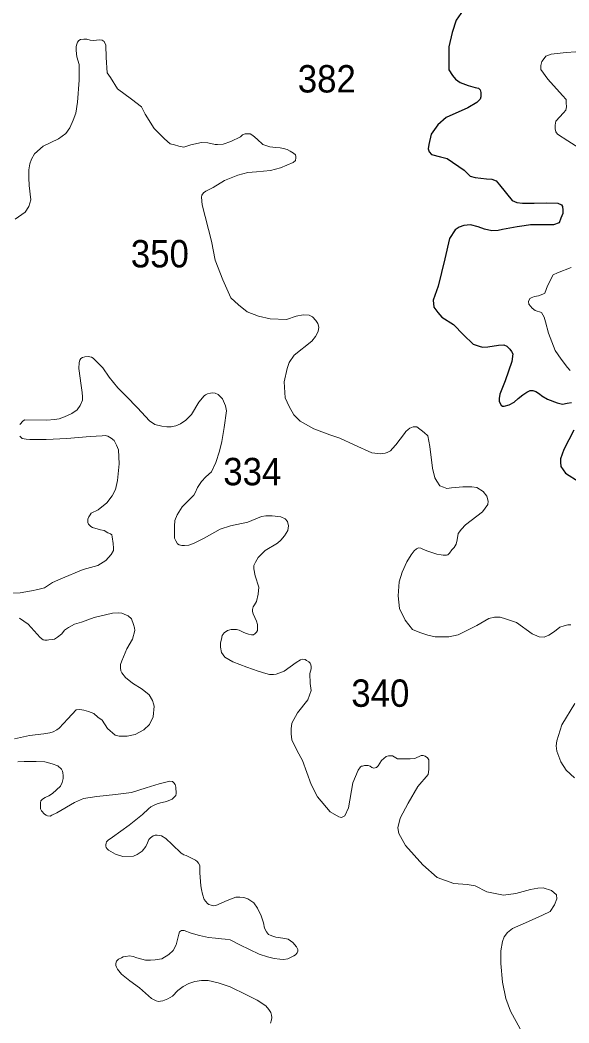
# Model space of a CAD drawing. Extents: x 445.4 to 500, y 8728.7 to 8784.
# Drawn here: x 471.62 to 474.83, y 8758.07 to 8763.93 of the extents above; entities that cross this region are included whole.
import ezdxf

# ---------------------------------------------------------------- set-up
doc = ezdxf.new("R2010")
doc.units = 0
doc.header["$LTSCALE"] = 0.064
doc.layers.add('1', color=7, linetype='Continuous', lineweight=25)
doc.layers.add('2', color=7, linetype='Continuous', lineweight=13)
doc.layers.add('21', color=7, linetype='Continuous')

msp = doc.modelspace()

# ---------------------------------------------------------------- linework, layer by layer
at = {"layer": '1'}
for points in [[(474.2089, 8763.9897), (474.1671, 8763.9313), (474.1437, 8763.8594), (474.1252, 8763.7747), (474.1252, 8763.6411), (474.147, 8763.6077), (474.1637, 8763.586), (474.1921, 8763.5659), (474.2373, 8763.5492), (474.2791, 8763.5376), (474.2992, 8763.5342), (474.3075, 8763.5242), (474.3125, 8763.5075), (474.3124, 8763.4831), (474.3073, 8763.4681), (474.2889, 8763.4497), (474.2354, 8763.418), (474.11, 8763.3628), (474.0615, 8763.3194), (474.0214, 8763.2643), (474.008, 8763.2042), (474.0046, 8763.1791), (474.0097, 8763.1608), (474.0247, 8763.1457), (474.0766, 8763.1324), (474.115, 8763.1223), (474.2146, 8763.0531), (474.2497, 8763.0197), (474.2781, 8763.0113), (474.345, 8763.003), (474.3768, 8763.0013), (474.4019, 8762.9913), (474.422, 8762.9679), (474.4955, 8762.8777), (474.5223, 8762.866), (474.5557, 8762.861), (474.6226, 8762.861), (474.6929, 8762.8627), (474.7614, 8762.861), (474.7832, 8762.851), (474.7899, 8762.8409), (474.7915, 8762.8209), (474.7915, 8762.8009), (474.7798, 8762.7741), (474.7698, 8762.7457), (474.7355, 8762.7354), (474.6017, 8762.7338), (474.5649, 8762.7288), (474.5248, 8762.7238), (474.4813, 8762.7154), (474.4379, 8762.7081), (474.4128, 8762.702), (474.376, 8762.7004), (474.3342, 8762.7087), (474.2957, 8762.7238), (474.2522, 8762.7354), (474.2121, 8762.7304), (474.1853, 8762.7204), (474.1619, 8762.7054), (474.1285, 8762.6553)], [(474.1285, 8762.6553), (474.1013, 8762.5356), (474.0628, 8762.3769), (474.0344, 8762.2951), (474.0377, 8762.2533), (474.0612, 8762.2216), (474.084, 8762.1943), (474.1526, 8762.1526), (474.2113, 8762.0908), (474.2663, 8762.0373), (474.3031, 8762.0257), (474.3215, 8762.0206), (474.3533, 8762.0223), (474.4151, 8762.0323), (474.4469, 8762.034), (474.4636, 8762.0257), (474.482, 8762.0089), (474.4921, 8761.9939), (474.4987, 8761.9806), (474.4938, 8761.9358), (474.4536, 8761.8223), (474.4235, 8761.7454), (474.4185, 8761.7204), (474.4185, 8761.702), (474.4302, 8761.6803), (474.4386, 8761.6753), (474.4489, 8761.6758), (474.477, 8761.682), (474.5071, 8761.6987), (474.5305, 8761.7199), (474.5573, 8761.7404), (474.5807, 8761.7571), (474.6008, 8761.7655), (474.6158, 8761.7672), (474.6342, 8761.7605), (474.6543, 8761.7471), (474.6677, 8761.7354), (474.7017, 8761.7154), (474.7569, 8761.6936), (474.7887, 8761.687), (474.8171, 8761.692), (474.8422, 8761.697)], [(474.8554, 8761.5339), (474.7969, 8761.422), (474.7768, 8761.3669), (474.7768, 8761.3468), (474.7801, 8761.3218), (474.8069, 8761.2834), (474.8855, 8761.2333)]]:
    msp.add_lwpolyline(points, dxfattribs=at)
at = {"layer": '2'}
for points in [[(471.5923, 8762.7668), (471.6508, 8762.8092), (471.6714, 8762.8413), (471.684, 8762.8813), (471.6748, 8762.9649), (471.6714, 8763.0084), (471.6718, 8763.0551), (471.6775, 8763.0906), (471.6879, 8763.1192), (471.7062, 8763.1501), (471.7566, 8763.1948), (471.8449, 8763.2371), (471.8884, 8763.268), (471.9125, 8763.3012), (471.932, 8763.347), (471.9474, 8763.3867), (471.9555, 8763.452), (471.9658, 8763.5802), (471.9658, 8763.6718), (471.9518, 8763.7173), (471.9495, 8763.754), (471.9495, 8763.7769), (471.9518, 8763.7906), (471.9564, 8763.802), (471.9644, 8763.8123), (471.9747, 8763.8181), (471.9942, 8763.8204)], [(471.9942, 8763.8204), (472.0114, 8763.8204), (472.0309, 8763.8135), (472.0481, 8763.8112), (472.0676, 8763.8135), (472.0836, 8763.8158), (472.1008, 8763.8146), (472.1123, 8763.8066), (472.1214, 8763.7837), (472.1237, 8763.7127), (472.1299, 8763.6238), (472.1482, 8763.5952), (472.1906, 8763.5288), (472.272, 8763.4681), (472.3293, 8763.4235), (472.3513, 8763.3816), (472.4051, 8763.2969), (472.4647, 8763.2373), (472.4968, 8763.2087), (472.5221, 8763.2018), (472.5473, 8763.1938), (472.5771, 8763.1892), (472.6183, 8763.2018), (472.6809, 8763.2164), (472.7176, 8763.2141), (472.76, 8763.2038), (472.7749, 8763.2038), (472.807, 8763.2061), (472.8528, 8763.2221), (472.909, 8763.2496), (472.9193, 8763.2599), (472.936, 8763.2665), (472.9518, 8763.2671), (472.9657, 8763.2665), (472.9803, 8763.2572), (473.0065, 8763.2345), (473.039, 8763.2037), (473.0794, 8763.1895), (473.1138, 8763.1871), (473.1399, 8763.1847), (473.1601, 8763.18), (473.1814, 8763.1753), (473.1992, 8763.1658), (473.2182, 8763.1527), (473.2289, 8763.1444), (473.2325, 8763.1349), (473.2325, 8763.1255), (473.2301, 8763.1112), (473.2159, 8763.0994), (473.1411, 8763.0685), (473.0829, 8763.0519), (473.0022, 8763.0448), (472.9512, 8763.0401), (472.893, 8763.0247), (472.8155, 8762.993), (472.7478, 8762.9527), (472.7051, 8762.9313), (472.6932, 8762.9218), (472.6825, 8762.9088), (472.6801, 8762.8957), (472.6849, 8762.8507), (472.7395, 8762.6384), (472.7611, 8762.5283), (472.805, 8762.4133), (472.8513, 8762.3089), (472.8964, 8762.2662), (472.9467, 8762.2262), (473.0132, 8762.2001), (473.0821, 8762.1847), (473.177, 8762.1823), (473.2328, 8762.2001), (473.2744, 8762.2084), (473.3088, 8762.2072), (473.329, 8762.1966), (473.348, 8762.1764), (473.361, 8762.1586), (473.3658, 8762.1361), (473.3622, 8762.1112), (473.3456, 8762.0827), (473.3242, 8762.0543), (473.221, 8761.9737), (473.1935, 8761.9303), (473.1804, 8761.8947), (473.1638, 8761.8177), (473.1685, 8761.724), (473.1923, 8761.673), (473.2196, 8761.6244), (473.2569, 8761.5878), (473.3364, 8761.5416), (473.4302, 8761.5072), (473.4895, 8761.4882), (473.5726, 8761.4491), (473.6747, 8761.4029), (473.71, 8761.3982), (473.7266, 8761.3958), (473.7527, 8761.4006), (473.7646, 8761.4041), (473.7836, 8761.4136), (473.7967, 8761.4267), (473.8157, 8761.4492), (473.8667, 8761.5144)], [(474.8846, 8763.1852), (474.8205, 8763.2255), (474.7592, 8763.2645), (474.7494, 8763.2784), (474.7452, 8763.2952), (474.7452, 8763.3174), (474.7508, 8763.3397), (474.794, 8763.3884), (474.808, 8763.4052), (474.8121, 8763.4246), (474.8107, 8763.4483), (474.8107, 8763.4678), (474.7886, 8763.491), (474.7036, 8763.5857), (474.6632, 8763.6428), (474.6632, 8763.6651), (474.6687, 8763.6887), (474.6757, 8763.6985), (474.691, 8763.7194), (474.7231, 8763.7319), (474.8095, 8763.7417), (474.9239, 8763.7486)], [(474.8344, 8761.8835), (474.8191, 8761.9002), (474.7814, 8761.9503), (474.7463, 8762.0001), (474.7073, 8762.1018), (474.6905, 8762.1686), (474.6822, 8762.1951), (474.6668, 8762.2215), (474.6292, 8762.2341), (474.6111, 8762.248), (474.5915, 8762.2716), (474.5901, 8762.287), (474.5985, 8762.3037), (474.6055, 8762.3078), (474.625, 8762.3162), (474.6487, 8762.319), (474.6738, 8762.3287), (474.685, 8762.3343), (474.7017, 8762.3789), (474.7351, 8762.4429), (474.7593, 8762.455), (474.8388, 8762.4843)], [(471.6204, 8761.5679), (471.6396, 8761.5897), (471.6487, 8761.5943), (471.7764, 8761.5934), (471.822, 8761.597), (471.8485, 8761.6007), (471.8804, 8761.6125), (471.9224, 8761.6317), (471.9543, 8761.6526), (471.9729, 8761.6796), (471.9848, 8761.7097), (471.9848, 8761.7297), (471.9839, 8761.7553), (471.9784, 8761.7954), (471.9638, 8761.8947), (471.9656, 8761.9292), (471.9702, 8761.9428), (471.9756, 8761.9528), (471.9857, 8761.9601), (471.9993, 8761.9638), (472.0194, 8761.9656), (472.0377, 8761.962)], [(472.0377, 8761.962), (472.0486, 8761.9547), (472.1043, 8761.8982), (472.1417, 8761.8444), (472.1913, 8761.7817), (472.2405, 8761.7334), (472.3062, 8761.665), (472.3765, 8761.5885), (472.4084, 8761.5684), (472.4486, 8761.5575), (472.4787, 8761.5547), (472.5042, 8761.5547), (472.5307, 8761.5602), (472.5571, 8761.572), (472.59, 8761.5939), (472.6218, 8761.6266), (472.6656, 8761.6977), (472.6957, 8761.736), (472.7048, 8761.7414), (472.7158, 8761.7469), (472.7322, 8761.7506), (472.7422, 8761.7524), (472.7605, 8761.7515), (472.7787, 8761.7433), (472.8024, 8761.7168), (472.8207, 8761.6767), (472.8262, 8761.6467), (472.8134, 8761.5501), (472.7997, 8761.4693), (472.7851, 8761.4119), (472.7641, 8761.3463), (472.7395, 8761.2907), (472.7055, 8761.2617), (472.68, 8761.2353), (472.6563, 8761.1997), (472.6444, 8761.1688), (472.6362, 8761.1542), (472.6161, 8761.136), (472.5669, 8761.0858), (472.5386, 8761.0394), (472.524, 8761.0065), (472.5238, 8760.973), (472.5238, 8760.9174), (472.5238, 8760.9037), (472.5311, 8760.8873), (472.5411, 8760.8709), (472.5511, 8760.8646), (472.5648, 8760.8609), (472.5812, 8760.8609), (472.6068, 8760.8618), (472.6369, 8760.8746), (472.6962, 8760.9028), (472.7902, 8760.9557), (472.8492, 8760.9761), (472.9514, 8760.9971), (473.0317, 8761.0299), (473.0573, 8761.0345), (473.0938, 8761.0345), (473.143, 8761.0281), (473.1686, 8761.0162), (473.1832, 8761.0007), (473.1895, 8760.9761), (473.185, 8760.9488), (473.1658, 8760.9178), (473.144, 8760.8916), (473.1249, 8760.8743), (473.0528, 8760.8305), (473.0117, 8760.7913), (472.9953, 8760.764), (472.9862, 8760.744), (472.9853, 8760.7248), (472.9944, 8760.6838), (473.0163, 8760.6164), (473.0108, 8760.5757), (473.0026, 8760.5338), (472.9898, 8760.5138), (472.9825, 8760.5028), (472.978, 8760.4864), (472.978, 8760.4755), (472.9816, 8760.4618), (473.0026, 8760.419), (473.0072, 8760.3991), (473.0081, 8760.3827), (473.0072, 8760.3645), (473.0017, 8760.3545), (472.9944, 8760.3472), (472.9835, 8760.339), (472.9735, 8760.3381), (472.9552, 8760.3417), (472.9379, 8760.3481), (472.9242, 8760.3545), (472.9132, 8760.36), (472.9005, 8760.3663), (472.8859, 8760.37), (472.8767, 8760.37), (472.8543, 8760.369), (472.8324, 8760.3636), (472.8132, 8760.3508), (472.8004, 8760.3344), (472.7968, 8760.3134), (472.7922, 8760.2916)], [(473.8667, 8761.5144), (473.8738, 8761.5274), (473.8869, 8761.5381), (473.8976, 8761.5464), (473.9177, 8761.5535), (473.9391, 8761.5535), (473.9807, 8761.5215), (474.002, 8761.5014), (474.0151, 8761.4385), (474.0293, 8761.3116), (474.0426, 8761.2563), (474.0545, 8761.2361), (474.0735, 8761.21), (474.0937, 8761.2017), (474.1138, 8761.1946), (474.1411, 8761.197), (474.2064, 8761.2041), (474.2598, 8761.2041), (474.2895, 8761.1993), (474.3251, 8761.1756), (474.3465, 8761.1495), (474.3548, 8761.1199), (474.3524, 8761.0997), (474.3216, 8761.0571), (474.2219, 8760.9812), (474.1994, 8760.9566), (474.1792, 8760.9305), (474.1733, 8760.8937), (474.1673, 8760.8688), (474.1566, 8760.8487), (474.1424, 8760.8344), (474.1293, 8760.8167), (474.1187, 8760.806), (474.1115, 8760.8048), (474.0925, 8760.8048), (474.0807, 8760.806), (474.0557, 8760.8095), (473.9964, 8760.8285), (473.9726, 8760.8392), (473.962, 8760.8451), (473.962, 8760.8451), (473.9477, 8760.8463), (473.937, 8760.8416), (473.9228, 8760.8285), (473.905, 8760.806), (473.8789, 8760.7657), (473.8523, 8760.7046), (473.8357, 8760.6477), (473.8297, 8760.5671), (473.8368, 8760.4924), (473.8701, 8760.4236), (473.9131, 8760.3705), (473.9557, 8760.3518), (474.0019, 8760.3364), (474.0454, 8760.3262), (474.089, 8760.3262), (474.1249, 8760.3262), (474.1788, 8760.339), (474.289, 8760.3928), (474.3583, 8760.4338), (474.3916, 8760.4414), (474.4249, 8760.4414), (474.4557, 8760.4312), (474.5198, 8760.4107), (474.6121, 8760.3441), (474.6531, 8760.3262), (474.6817, 8760.3246), (474.7083, 8760.3361), (474.7419, 8760.3581), (474.7743, 8760.3824), (474.7986, 8760.3917), (474.8206, 8760.3963), (474.838, 8760.3963)], [(471.5724, 8760.5812), (471.6217, 8760.5839), (471.6874, 8760.5948), (471.7239, 8760.6039), (471.7631, 8760.614), (471.8113, 8760.6445), (471.8587, 8760.6664), (471.9901, 8760.7202), (472.0749, 8760.7439), (472.1224, 8760.773), (472.1534, 8760.8076), (472.1662, 8760.8304), (472.1662, 8760.8459), (472.1643, 8760.8724), (472.1581, 8760.9105), (472.1563, 8760.9223), (472.1499, 8760.9287), (472.1344, 8760.9351), (472.1116, 8760.9478), (472.0906, 8760.9515), (472.0432, 8760.966), (472.0341, 8760.9724), (472.0259, 8760.9797), (472.0213, 8760.9861), (472.0158, 8760.9952), (472.0158, 8761.0052), (472.0176, 8761.0153), (472.0222, 8761.028), (472.0295, 8761.0399), (472.0359, 8761.049), (472.0779, 8761.069), (472.128, 8761.11), (472.1581, 8761.151), (472.1783, 8761.1881), (472.1902, 8761.2401), (472.1993, 8761.3376), (472.1957, 8761.4202), (472.1847, 8761.4467), (472.1711, 8761.474), (472.1537, 8761.4886), (472.1336, 8761.4995), (472.1172, 8761.5032), (472.1008, 8761.5022), (472.0296, 8761.4977), (471.8941, 8761.4859), (471.7728, 8761.4804), (471.7098, 8761.4795), (471.6779, 8761.4795), (471.6569, 8761.4813), (471.6341, 8761.4868), (471.625, 8761.4941), (471.6204, 8761.5004)], [(471.5884, 8759.7315), (471.6752, 8759.7493), (471.759, 8759.7602), (471.7954, 8759.7665), (471.8136, 8759.772), (471.8354, 8759.7829), (471.85, 8759.7938), (471.8992, 8759.8466), (471.9492, 8759.8993), (471.9709, 8759.902), (471.993, 8759.8986), (472.0202, 8759.8901), (472.0509, 8759.8782), (472.0747, 8759.8578), (472.1003, 8759.8391), (472.1309, 8759.7915), (472.1769, 8759.7523), (472.2007, 8759.7455), (472.216, 8759.7455), (472.2467, 8759.7455), (472.2926, 8759.7557), (472.3437, 8759.783), (472.3778, 8759.8136), (472.3982, 8759.8595), (472.404, 8759.9216), (472.4003, 8759.9343), (472.3939, 8759.9553), (472.3748, 8759.9872), (472.3346, 8760.0218), (472.2781, 8760.0565), (472.2368, 8760.089), (472.2149, 8760.1155), (472.2085, 8760.1282), (472.2067, 8760.1465), (472.2076, 8760.1647), (472.2149, 8760.1856), (472.245, 8760.2567), (472.2778, 8760.3132), (472.2907, 8760.3632), (472.2889, 8760.3787), (472.2834, 8760.3996), (472.2715, 8760.4315), (472.2524, 8760.4497), (472.2287, 8760.4598), (472.215, 8760.4643), (472.1958, 8760.4661), (472.1602, 8760.4652), (472.0535, 8760.4388), (471.9789, 8760.4131), (471.9388, 8760.4003), (471.9032, 8760.3812), (471.8804, 8760.3648), (471.8649, 8760.3447), (471.8393, 8760.3256), (471.8229, 8760.3137), (471.812, 8760.311), (471.7891, 8760.3083)], [(471.7891, 8760.3083), (471.78, 8760.3074), (471.7663, 8760.3074), (471.7563, 8760.3092), (471.739, 8760.3229), (471.6678, 8760.4012), (471.6185, 8760.4368)], [(472.7922, 8760.2916), (472.7922, 8760.266), (472.7977, 8760.2351), (472.8169, 8760.2077), (472.8634, 8760.1804), (472.9455, 8760.1503), (473.0109, 8760.1253), (473.0556, 8760.1126), (473.0784, 8760.1071), (473.1012, 8760.1062), (473.1176, 8760.1089), (473.1642, 8760.1253), (473.2335, 8760.1763), (473.259, 8760.1927), (473.2718, 8760.1955), (473.2855, 8760.1937), (473.2937, 8760.1891), (473.3083, 8760.1809), (473.3147, 8760.1727), (473.3193, 8760.1627), (473.3202, 8760.1536), (473.3202, 8760.1399), (473.3129, 8760.1126), (473.3156, 8760.0533), (473.3211, 8760.0132), (473.3007, 8759.9584), (473.2407, 8759.8835), (473.2085, 8759.8214), (473.2042, 8759.7892), (473.2042, 8759.7593), (473.2085, 8759.725), (473.2385, 8759.6607), (473.271, 8759.6037), (473.3203, 8759.4645), (473.3589, 8759.3917), (473.4318, 8759.3039), (473.4832, 8759.2739), (473.4982, 8759.2718), (473.5175, 8759.2803), (473.539, 8759.3275), (473.5647, 8759.4731), (473.5962, 8759.5482), (473.6083, 8759.5669), (473.6149, 8759.5713), (473.6204, 8759.5713), (473.6325, 8759.5757), (473.6534, 8759.5757), (473.6666, 8759.5702), (473.6754, 8759.5636), (473.6864, 8759.5592), (473.7018, 8759.5625), (473.7128, 8759.5735), (473.7315, 8759.6031), (473.76, 8759.6273), (473.7721, 8759.6317), (473.7952, 8759.6306), (473.8249, 8759.6141), (473.8601, 8759.613), (473.8986, 8759.613), (473.9261, 8759.6152), (473.9636, 8759.6341), (473.975, 8759.6341), (473.9865, 8759.6284), (473.9865, 8759.6284), (473.9998, 8759.6189), (474.0074, 8759.6075), (474.0074, 8759.5505), (474.0036, 8759.522), (473.9446, 8759.4517), (473.8875, 8759.3548), (473.84, 8759.2674), (473.8267, 8759.2104), (473.8328, 8759.1765), (473.8728, 8759.1081), (473.9736, 8758.9941), (474.0573, 8758.92), (474.1543, 8758.8858), (474.2323, 8758.8801), (474.2798, 8758.8725), (474.3464, 8758.8364), (474.4453, 8758.8174), (474.5167, 8758.8267), (474.6023, 8758.8495), (474.6441, 8758.8571), (474.6764, 8758.859), (474.724, 8758.8438), (474.7544, 8758.8191), (474.7553, 8758.795), (474.7419, 8758.7609), (474.716, 8758.7216), (474.6725, 8758.7009), (474.5897, 8758.6637), (474.4966, 8758.6213), (474.4676, 8758.5996), (474.4479, 8758.5737), (474.4386, 8758.5469), (474.4283, 8758.491), (474.4283, 8758.4179), (474.4386, 8758.3083), (474.4572, 8758.2132), (474.4853, 8758.139)], [(474.8612, 8759.9374), (474.7848, 8759.8125), (474.7566, 8759.718), (474.752, 8759.6891), (474.7554, 8759.659), (474.7797, 8759.5966)], [(471.8349, 8759.298), (471.8058, 8759.2844), (471.7976, 8759.2789), (471.7803, 8759.2799), (471.773, 8759.2853), (471.763, 8759.2899), (471.7457, 8759.3099), (471.7412, 8759.3217), (471.7403, 8759.3381), (471.7412, 8759.3562), (471.743, 8759.369), (471.7521, 8759.3781), (471.7676, 8759.3872), (471.7894, 8759.3981), (471.8095, 8759.4117), (471.8568, 8759.4545), (471.8668, 8759.4754), (471.873, 8759.4987), (471.8721, 8759.5169), (471.8712, 8759.5324), (471.8685, 8759.5424), (471.8621, 8759.5533), (471.8412, 8759.5733), (471.8093, 8759.5842), (471.7656, 8759.5961), (471.7146, 8759.5988), (471.6445, 8759.5979), (471.6081, 8759.597)], [(474.7797, 8759.5966), (474.811, 8759.548), (474.8596, 8759.5029)], [(473.1054, 8758.4474), (473.1388, 8758.4424), (473.1588, 8758.4407), (473.1855, 8758.4457), (473.2198, 8758.4625), (473.2298, 8758.4691), (473.2398, 8758.4791), (473.2431, 8758.4891), (473.2431, 8758.4991), (473.2348, 8758.5141), (473.2131, 8758.5408), (473.1864, 8758.5591), (473.1564, 8758.5658), (473.1146, 8758.5708), (473.098, 8758.5775), (473.0813, 8758.5825), (473.0713, 8758.5875), (473.0596, 8758.6025), (473.0479, 8758.6242), (473.0425, 8758.6562), (473.0288, 8758.6962), (473.0079, 8758.7417), (472.987, 8758.7726), (472.9505, 8758.7953), (472.9269, 8758.8035), (472.9041, 8758.8053), (472.8804, 8758.8044), (472.8304, 8758.7853), (472.7648, 8758.7571), (472.7521, 8758.7553), (472.7375, 8758.758), (472.7238, 8758.7617), (472.7166, 8758.768), (472.6965, 8758.7926), (472.6874, 8758.8235), (472.681, 8758.8508), (472.6765, 8758.8717), (472.6718, 8758.9478), (472.6709, 8758.9724), (472.6709, 8758.9897), (472.6636, 8759.0042), (472.6554, 8759.0133), (472.6463, 8759.0224), (472.619, 8759.0361), (472.5916, 8759.0479), (472.5771, 8759.0533), (472.5707, 8759.057), (472.5616, 8759.0633), (472.5094, 8759.1138), (472.473, 8759.1484), (472.4466, 8759.1629), (472.4338, 8759.1665), (472.422, 8759.1684), (472.4093, 8759.1674), (472.3992, 8759.1647), (472.3829, 8759.1529), (472.3728, 8759.142), (472.3646, 8759.122), (472.3555, 8759.1011), (472.3337, 8759.0747), (472.3055, 8759.0556), (472.2836, 8759.0456), (472.2217, 8759.0429), (472.1783, 8759.0574), (472.151, 8759.0719), (472.1383, 8759.0792), (472.1301, 8759.0874), (472.1246, 8759.0965), (472.1228, 8759.1038), (472.1219, 8759.1111), (472.1237, 8759.1211), (472.1264, 8759.1292), (472.1346, 8759.1383), (472.1601, 8759.1556), (472.2575, 8759.2256), (472.3358, 8759.2893), (472.371, 8759.3208), (472.3847, 8759.3335), (472.401, 8759.3408), (472.422, 8759.3499), (472.442, 8759.3562), (472.4684, 8759.3626), (472.4857, 8759.369), (472.5094, 8759.3781), (472.5194, 8759.3872), (472.5258, 8759.3944), (472.5303, 8759.399), (472.533, 8759.4108), (472.5312, 8759.449), (472.5267, 8759.4636), (472.5185, 8759.4736), (472.5121, 8759.4817), (472.4957, 8759.4836), (472.4329, 8759.4681), (472.3582, 8759.4445), (472.2708, 8759.4172), (472.1782, 8759.4044), (472.0698, 8759.3944), (471.9906, 8759.3826), (471.9396, 8759.359), (471.8349, 8759.298)], [(473.0835, 8758.0696), (473.0889, 8758.0875), (473.0907, 8758.1028), (473.0898, 8758.1162), (473.0853, 8758.1305), (473.0736, 8758.1494), (473.0557, 8758.1709), (473.0053, 8758.2038), (472.9443, 8758.2351), (472.8483, 8758.2817), (472.7783, 8758.305), (472.72, 8758.3176), (472.6814, 8758.3176), (472.6419, 8758.3122), (472.6061, 8758.3006), (472.5732, 8758.2834), (472.5418, 8758.2592), (472.5104, 8758.2269), (472.4834, 8758.2117), (472.4646, 8758.2036), (472.4538, 8758.2), (472.4413, 8758.1982), (472.4287, 8758.1964), (472.4161, 8758.2), (472.3892, 8758.2135), (472.3193, 8758.2753), (472.2627, 8758.3156), (472.2134, 8758.3551), (472.1899, 8758.3842), (472.1846, 8758.3959), (472.1801, 8758.4058), (472.1801, 8758.4174), (472.1837, 8758.4317), (472.1962, 8758.4425), (472.2124, 8758.4515), (472.224, 8758.4559), (472.2393, 8758.4595), (472.2608, 8758.4622), (472.2824, 8758.4595), (472.3021, 8758.4506), (472.3532, 8758.438), (472.3819, 8758.438), (472.4098, 8758.4398), (472.4483, 8758.4443), (472.4905, 8758.4703), (472.5156, 8758.4936), (472.5336, 8758.5276), (472.5479, 8758.5886), (472.5524, 8758.6029), (472.5641, 8758.611), (472.5793, 8758.6101), (472.6201, 8758.5943), (472.6685, 8758.5818), (472.7215, 8758.5692), (472.7618, 8758.5657), (472.7977, 8758.5621), (472.8192, 8758.5603), (472.8471, 8758.5567), (472.9051, 8758.5274), (473.017, 8758.4724), (473.067, 8758.4557), (473.1054, 8758.4474)], [(474.4853, 8758.139), (474.5412, 8758.0356)]]:
    msp.add_lwpolyline(points, dxfattribs=at)

# ---------------------------------------------------------------- texts
at = {"layer": '21', "width": 0.95}
for s, p in [('382', (473.2429, 8763.508)), ('350', (472.2678, 8762.4858)), ('334', (472.8078, 8761.2126)), ('340', (473.5556, 8759.9177))]:
    msp.add_text(s, height=0.16, dxfattribs=at).set_placement(p)

doc.saveas('drawing.dxf')
